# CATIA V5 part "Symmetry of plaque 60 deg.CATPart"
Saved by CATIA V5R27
Part number: Symmetry of plaque 60 deg
Material "Aluminium": density 2710 kg/m3, Young's modulus 7e+10 Pa, Poisson ratio 0.346, thermal expansion 2.36e-05 1/K
Bounding box of the stored display mesh (mm): x 0 to 6, y -175.081 to -24.919, z 0 to 200
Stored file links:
  \\triton.meca.polymtl.ca\usagers\zaoue\profiles\Desktop\varm_ass\structure prismatique\Symmetry of plaque 60 deg.CATPart
  \\triton.meca.polymtl.ca\usagers\zaoue\profiles\Desktop\varm_ass\structure prismatique\plaque 60 deg.CATPart
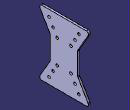
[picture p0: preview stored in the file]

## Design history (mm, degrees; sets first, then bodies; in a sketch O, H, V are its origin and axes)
Body1 (main body)
  Body2 "Corps du corps principal d'origine", material "Aluminium"
    Solid1: linked copy from another document
  Assemble1: tool Body2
